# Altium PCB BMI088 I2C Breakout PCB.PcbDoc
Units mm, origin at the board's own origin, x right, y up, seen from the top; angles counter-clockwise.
Board outline 10.78 x 13.65 mm, 2 copper layers (Top Layer, Bottom Layer); 9 components, 10 nets, 36 pads, 4 vias.
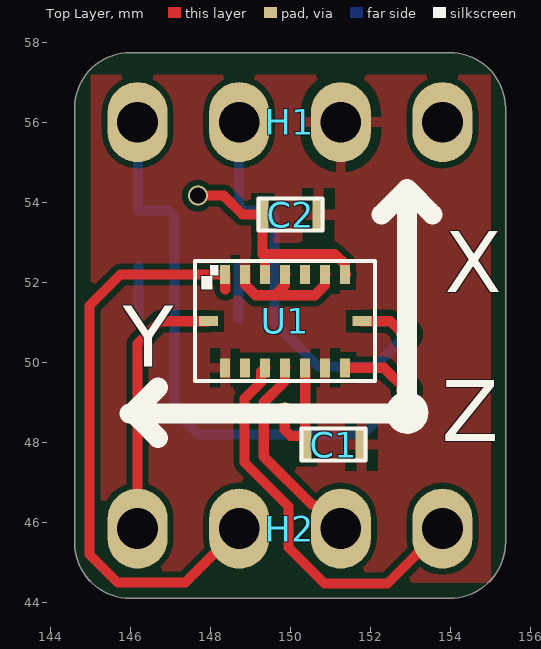
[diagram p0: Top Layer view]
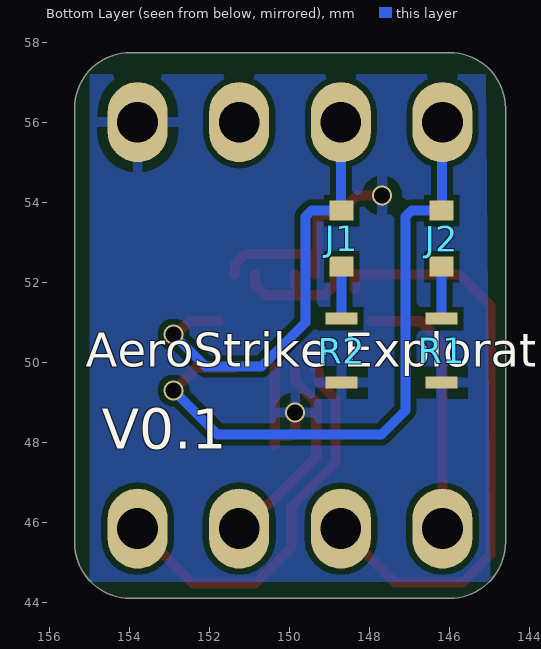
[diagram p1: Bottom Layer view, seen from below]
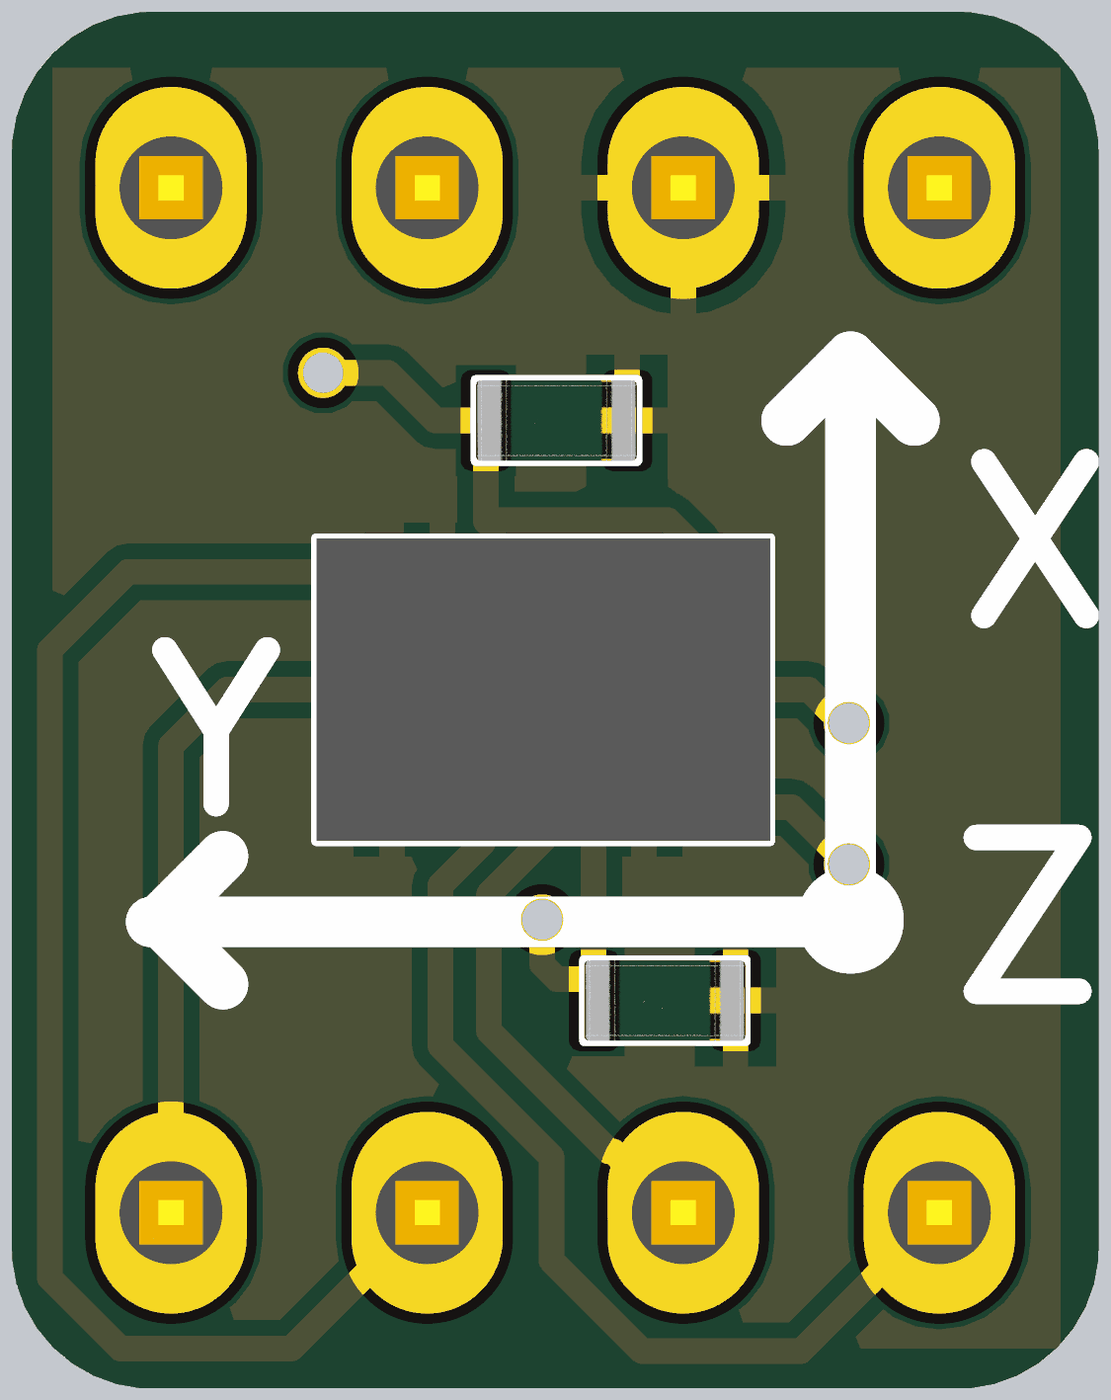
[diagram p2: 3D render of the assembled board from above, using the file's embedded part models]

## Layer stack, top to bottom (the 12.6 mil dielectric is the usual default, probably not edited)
Top Solder: solder mask 0.0102, Solder Resist, Dk 3.5
Top Layer: signal copper 0.0356
Dielectric 1: dielectric 0.32, FR-4, Dk 4.8
Bottom Layer: signal copper 0.0356
Bottom Solder: solder mask 0.0102, Solder Resist, Dk 3.5

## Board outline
144.6,45.504 ccw(c146,45.504) 146,44.104 153.975,44.104 ccw(c153.975,45.504) 155.375,45.504 155.375,56.35 ccw(c153.975,56.35) 153.975,57.75 146,57.75 ccw(c146,56.35) 144.6,56.35

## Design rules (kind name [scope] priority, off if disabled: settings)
Clearance [All] p1: gap=0.15 ignorepadtopadclearanceinfootprint=FALSE
HoleSize [All] p1: absolutevalues=TRUE maxlimit=6.25 minlimit=0.35 maxpercent=80.000 minpercent=20.000
PolygonConnect [All] p1: connectstyle=Relief reliefconductorwidth=0.254 reliefentries=4 polygonreliefangle="90 Angle" airgapwidth=0.254
RoutingVias [All] p1: holewidth=4 width=1.27 viastyle="Through Hole" minholewidth=0.35 minwidth=1.27 maxholewidth=6.25 maxwidth=1.27
SolderMaskExpansion [All] p1: expansion=0.102 istentingtop=FALSE
Width [All] p1: maxlimit=0.254 minlimit=0.254 preferedwidth=0.254
29 further rules are at their usual default settings.

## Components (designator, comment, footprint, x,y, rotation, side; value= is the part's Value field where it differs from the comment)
C1 "0.1uF" "CL10B104KB8NNWC 0.1uF 0603-Footprint-1" 151.075,47.95 r180 top
C2 "0.1uF" "CL10B104KB8NNWC 0.1uF 0603-Footprint-1" 150,53.7 r180 top
H1 "PR20204VBNN 4 Pin Male Header Pin 2.54mm" "PR20204VBNN 4 Pin Male Header Pin 2.54mm-Footprint-1" 149.987,56.007 r180 top
H2 "PR20204VBNN 4 Pin Male Header Pin 2.54mm" "PR20204VBNN 4 Pin Male Header Pin 2.54mm-Footprint-1" 149.987,45.847 r0 top
J1 "Jumpers" "Small Jumper-Footprint-1" 148.7,53.1 r270 bottom
J2 "Small Jumper" "Small Jumper-Footprint-1" 146.2,53.1 r270 bottom
R1 "WR06X152 JTL 1.5K Ohm 0603" "WR06X152 JTL 1.5K Ohm 0603-Footprint-1" 146.2,50.3 r90 bottom value="1.5K Ohm"
R2 "WR06X152 JTL 1.5K Ohm 0603" "WR06X152 JTL 1.5K Ohm 0603-Footprint-1" 148.7,50.3 r90 bottom value="1.5K Ohm"
U1 "BMI088 IMU" "BMI088 IMU-Footprint-1" 149.868,51.032 r0 top

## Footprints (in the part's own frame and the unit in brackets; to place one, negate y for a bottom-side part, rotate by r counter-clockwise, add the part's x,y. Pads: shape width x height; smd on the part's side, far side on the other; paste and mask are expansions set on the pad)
"BMI088 IMU-Footprint-1" [mm]
  rect 0.25x0.475 smd mask+0.03: 1(-1.5,1.165) 2(-1,1.165) 3(-0.5,1.165) 4(0,1.165) 5(0.5,1.165) 6(1,1.165) 7(1.5,1.165) 9(1.5,-1.165) 10(1,-1.165) 11(0.5,-1.165) 12(0,-1.165) 13(-0.5,-1.165) 14(-1,-1.165) 15(-1.5,-1.165)
  rect 0.475x0.25 smd mask+0.03: 8(1.915,0) 16(-1.915,0)
  silkscreen extent -3.89,-2.92 3.68,3.3, body extent -2.25,-1.5 2.25,1.5, height 1
"CL10B104KB8NNWC 0.1uF 0603-Footprint-1" [mm]
  rect 0.3x0.8 smd: 1(-0.7,0) 2(0.7,0)
  silkscreen extent -0.8,-0.4 0.8,0.4, body extent -0.8,-0.4 0.8,0.4, height 0.9
"PR20204VBNN 4 Pin Male Header Pin 2.54mm-Footprint-1" [mm]
  oval 1.5x2 hole 1.02: 1(-3.81,0) 2(-1.27,0) 3(1.27,0) 4(3.81,0)
  body extent -5.08,-1.27 5.08,1.27, height 2.8
"Small Jumper-Footprint-1" [mm]
  rect 0.5x0.6 smd: 1(-0.7,0) 2(0.7,0)
"WR06X152 JTL 1.5K Ohm 0603-Footprint-1" [mm]
  rect 0.3x0.8 smd: 1(-0.8,0) 2(0.8,0)
  body extent -0.85,-0.44 0.85,0.44, height 0.56

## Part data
C1 C2: library part CMP-00001-6, "CL10B104KB8NNWC 0.1uF 0603 +-10% SMD"
H1 H2: library part CMP-00002-5, "PR20204VBNN 4 Pin Male Header Pin 2.54mm General Use"
J1 J2: library part CMP-00004-3, "Small Jumper For Low Current And Voltage"
R1 R2: library part CMP-00003-4, "WR06X152 JTL 1.5K Ohm 0603 +-5% SMD"
U1: library part CMP-00000-17, "BMI088 IMU General Use"

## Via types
v1: diameter 0.5, hole 0.4, Top Layer to Bottom Layer, 4 vias

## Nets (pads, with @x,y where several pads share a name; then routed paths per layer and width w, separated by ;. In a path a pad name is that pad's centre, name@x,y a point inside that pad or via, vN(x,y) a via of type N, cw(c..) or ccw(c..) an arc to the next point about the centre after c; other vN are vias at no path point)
+3V3: C1.2 C2.2 H1.1 R1.1 R2.1 U1.3 U1.7 U1.11 | length 8.9
  Top Layer w0.254: v1(147.685,54.173) 148.327,54.173 148.8,53.7 C2.2 149.3,52.7 ; U1.3 149.366,52.199 149.366,52.634 149.3,52.7 ; v1(149.857,48.752) 149.857,48.311 150.006,48.162 150.352,48.162 150.375,48.139 C1.2 ; U1.11 150.368,47.959 C1.2 ; U1.7 151.366,52.199 151.366,52.453 151.108,52.711 149.311,52.711 149.3,52.7 ; U1.7@151.374,52.197 U1.7@151.384,52.207
GND: C1.1 C2.1 H1.2 U1.2 U1.4 U1.6 U1.10 U1.15 | length 3.3
  Top Layer w0.254: U1.2 148.87,52.195 148.87,51.941 149.128,51.683 149.608,51.683 ; U1.4 149.866,52.195 149.866,51.941 149.608,51.683 ; U1.6 150.866,52.195 150.866,51.941 150.608,51.683 149.608,51.683
INT1: H2.1 U1.16 | length 6.8
  Top Layer w0.254: H2.1@146.177,45.72 146.177,50.477 146.732,51.032 U1.16
INT2: H2.2 U1.1 | length 14.9
  Top Layer w0.254: 148.37,51.825 148.37,52.195 U1.1 148.365,52.2 145.75,52.2 144.975,51.425 144.975,45.2 145.675,44.5 147.37,44.5 H2.2
INT3: H2.3 U1.12 | length 5.2
  Top Layer w0.254: U1.12 149.866,49.865 149.866,49.539 149.33,49.004 149.33,47.647 150.523,46.454 150.563,46.454 151.257,45.76 H2.3@151.257,45.72
INT4: H2.4 U1.13 | length 10
  Top Layer w0.254: U1.13 149.27,49.769 149.27,49.515 148.849,49.093 148.849,47.501 149.95,46.4 149.95,45.375 150.85,44.475 152.425,44.475 H2.4
NetJ1_2: J1.2 R2.2 | length 1.3
  Bottom Layer w0.254: R2.2 J1.2
NetJ2_2: J2.2 R1.2 | length 1.3
  Bottom Layer w0.254: R1.2 J2.2
SCL: H1.3 J1.1 U1.8 | length 11.4
  Top Layer w0.254: H1.3@148.717,55.757 H1.3 ; U1.8 152.501,51.032 152.833,50.7 v1(152.9,50.7)
  Bottom Layer w0.254: H1.3 148.709,55.999 148.709,53.809 J1.1 149.451,53.8 149.6,53.651 149.6,51 150.7,49.9 152.1,49.9 v1(152.9,50.7)
SDA: H1.4 J2.1 U1.9 | length 16.3
  Top Layer w0.254: U1.9@151.374,49.867 152.333,49.867 v1(152.9,49.3)
  Bottom Layer w0.254: H1.4 146.189,55.995 146.189,53.812 J2.1 146.951,53.8 147.1,53.651 147.1,48.8 147.7,48.2 151.8,48.2 v1(152.9,49.3) v1@152.9,49.255
pads on no net: U1.5 U1.14

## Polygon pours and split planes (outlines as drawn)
+3V3 on Bottom Layer "+3V3_L02_P001" (solid, pour order 1): 145.1,57.206 154.996,57.206 154.996,44.521 144.978,44.521
GND on Top Layer "GND_L01_P000" (solid, pour order 0): 145,57.2 145,44.5 155,44.5 155,57.2

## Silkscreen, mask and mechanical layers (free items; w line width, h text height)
Bottom Overlay:
  text "AeroStrike Exploration Technologies" at 155.1,49.9 h0.85
  text "V0.1" at 154.7,47.85 h1
Mechanical 1:
  the board outline again, w0.1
